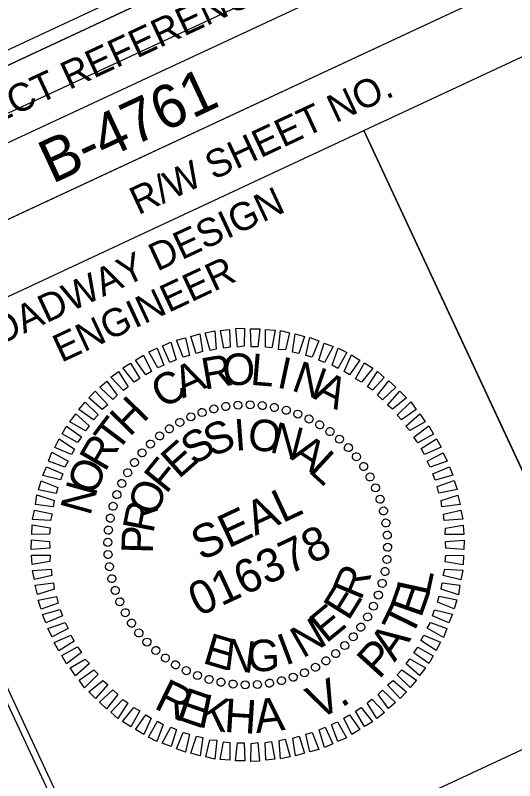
# Model space of a CAD drawing. Extents: x 2320593 to 2322597, y 921119 to 922832.
# Drawn here: x 2321990.9 to 2322080.4, y 922602.4 to 922739.5 of the extents above; entities that cross this region are included whole.
import ezdxf

# ---------------------------------------------------------------- set-up
doc = ezdxf.new("R2010")
doc.units = 0
for name, color, linetype in [('Prop Leader Line Medium', 7, 'Continuous'), ('Sheet Data Field CELL', 7, 'Continuous'), ('Sheet Layout Plan Border', 7, 'Continuous'), ('Sheet Plan And Profile CELL', 7, 'Continuous'), ('Sheet Plot Border Inside CELL', 7, 'Continuous'), ('Sheet Professional Seal CELL', 7, 'Continuous')]:
    doc.layers.add(name, color=color, linetype=linetype)

msp = doc.modelspace()

# ---------------------------------------------------------------- linework, layer by layer
at = {"layer": 'Prop Leader Line Medium'}
msp.add_lwpolyline([(2321590.4, 922532.13), (2321950.44, 922699.95), (2322002.96, 922587.28), (2321642.92, 922419.46)], close=True, dxfattribs=at)
at = {"layer": 'Sheet Layout Plan Border'}
msp.add_lwpolyline([(2322313.35, 922279.99), (2321040.83, 921692.7), (2320815.91, 922178.3), (2322085.86, 922766.57)], close=True, dxfattribs=at)
at = {"layer": 'Sheet Plan And Profile CELL'}
for p, q in [((2321952.14, 922699.22), (2322133.46, 922783.74)), ((2321957.42, 922687.9), (2322138.74, 922772.41)), ((2322053.38, 922718.83), (2322100.89, 922616.91))]:
    msp.add_line(p, q, dxfattribs=at)
for points in [[(2322128.15, 922795.12), (2320768.59, 922161.4), (2321212.2, 921209.71), (2322571.76, 921843.43)], [(2321946.83, 922710.6), (2322128.15, 922795.12), (2322138.74, 922772.41), (2321957.42, 922687.9)], [(2322053.38, 922718.83), (2322144.02, 922761.08), (2322191.55, 922659.12), (2322100.91, 922616.87)], [(2321962.7, 922676.57), (2322053.38, 922718.83), (2322100.91, 922616.87), (2322010.23, 922574.6)]]:
    msp.add_lwpolyline(points, close=True, dxfattribs=at)
at = {"layer": 'Sheet Plot Border Inside CELL'}
msp.add_lwpolyline([(2321074.13, 921142.59), (2322584.14, 921846.44), (2322138.43, 922802.66), (2320628.41, 922098.81)], close=True, dxfattribs=at)
at = {"layer": 'Sheet Professional Seal CELL'}
for p, q in [((2322028.63, 922669.42), (2322028.63, 922669.42)), ((2322030.82, 922669.67), (2322030.82, 922669.67)), ((2322033.02, 922669.7), (2322033.02, 922669.7)), ((2322035.21, 922669.62), (2322035.21, 922669.62)), ((2322024.44, 922668.35), (2322024.44, 922668.35)), ((2322026.53, 922668.94), (2322026.53, 922668.94)), ((2322037.37, 922669.24), (2322037.37, 922669.24)), ((2322039.52, 922668.76), (2322039.52, 922668.76)), ((2322041.56, 922668.06), (2322041.56, 922668.06)), ((2322020.41, 922666.58), (2322020.41, 922666.58)), ((2322022.38, 922667.55), (2322022.38, 922667.55)), ((2322043.62, 922667.19), (2322043.62, 922667.19)), ((2322018.58, 922665.4), (2322018.58, 922665.4)), ((2322045.49, 922666.14), (2322045.49, 922666.14)), ((2322016.76, 922664.11), (2322016.76, 922664.11)), ((2322047.34, 922664.9), (2322047.34, 922664.9)), ((2322015.11, 922662.68), (2322015.11, 922662.68)), ((2322049.07, 922663.55), (2322049.07, 922663.55)), ((2322013.63, 922661.11), (2322013.63, 922661.11)), ((2322050.64, 922662.08), (2322050.64, 922662.08)), ((2322052.07, 922660.43), (2322052.07, 922660.43)), ((2322012.29, 922659.38), (2322012.29, 922659.38)), ((2322053.36, 922658.61), (2322053.36, 922658.61)), ((2322011.05, 922657.53), (2322011.05, 922657.53)), ((2322009.99, 922655.66), (2322009.99, 922655.66)), ((2322054.54, 922656.78), (2322054.54, 922656.78)), ((2322055.51, 922654.81), (2322055.51, 922654.81)), ((2322009.13, 922653.6), (2322009.13, 922653.6)), ((2322008.43, 922651.56), (2322008.43, 922651.56)), ((2322056.31, 922652.75), (2322056.31, 922652.75)), ((2322056.9, 922650.66), (2322056.9, 922650.66)), ((2322007.94, 922649.41), (2322007.94, 922649.41)), ((2322057.38, 922648.56), (2322057.38, 922648.56)), ((2322007.57, 922647.25), (2322007.57, 922647.25)), ((2322057.63, 922646.36), (2322057.63, 922646.36)), ((2322007.49, 922645.06), (2322007.49, 922645.06)), ((2322032.57, 922644.61), (2322032.57, 922644.61)), ((2322057.66, 922644.17), (2322057.66, 922644.17)), ((2322007.52, 922642.86), (2322007.52, 922642.86)), ((2322057.58, 922641.98), (2322057.58, 922641.98)), ((2322007.77, 922640.67), (2322007.77, 922640.67)), ((2322057.21, 922639.82), (2322057.21, 922639.82)), ((2322008.25, 922638.57), (2322008.25, 922638.57)), ((2322008.84, 922636.48), (2322008.84, 922636.48)), ((2322056.72, 922637.66), (2322056.72, 922637.66)), ((2322056.02, 922635.63), (2322056.02, 922635.63)), ((2322009.63, 922634.42), (2322009.63, 922634.42)), ((2322010.61, 922632.44), (2322010.61, 922632.44)), ((2322055.15, 922633.57), (2322055.15, 922633.57)), ((2322054.1, 922631.7), (2322054.1, 922631.7)), ((2322011.79, 922630.62), (2322011.79, 922630.62)), ((2322052.86, 922629.85), (2322052.86, 922629.85)), ((2322013.08, 922628.8), (2322013.08, 922628.8)), ((2322051.52, 922628.12), (2322051.52, 922628.12)), ((2322014.51, 922627.15), (2322014.51, 922627.15)), ((2322016.08, 922625.67), (2322016.08, 922625.67)), ((2322050.04, 922626.55), (2322050.04, 922626.55)), ((2322017.81, 922624.33), (2322017.81, 922624.33)), ((2322048.39, 922625.12), (2322048.39, 922625.12)), ((2322019.66, 922623.09), (2322019.66, 922623.09)), ((2322044.74, 922622.65), (2322044.74, 922622.65)), ((2322046.57, 922623.83), (2322046.57, 922623.83)), ((2322021.53, 922622.03), (2322021.53, 922622.03)), ((2322042.77, 922621.67), (2322042.77, 922621.67)), ((2322023.59, 922621.17), (2322023.59, 922621.17)), ((2322025.63, 922620.47), (2322025.63, 922620.47)), ((2322027.78, 922619.98), (2322027.78, 922619.98)), ((2322038.62, 922620.29), (2322038.62, 922620.29)), ((2322040.71, 922620.88), (2322040.71, 922620.88)), ((2322029.94, 922619.61), (2322029.94, 922619.61)), ((2322032.13, 922619.53), (2322032.13, 922619.53)), ((2322034.32, 922619.56), (2322034.32, 922619.56)), ((2322036.52, 922619.81), (2322036.52, 922619.81))]:
    msp.add_line(p, q, dxfattribs=at)
for points in [[(2322025.88, 922679.45), (2322024.96, 922682.6), (2322026.67, 922682.96), (2322026.94, 922679.66)], [(2322028.33, 922679.87), (2322027.7, 922683), (2322029.32, 922683.2), (2322029.43, 922680)], [(2322030.75, 922680.01), (2322030.46, 922683.35), (2322031.98, 922683.4), (2322031.94, 922680.18)], [(2322033.19, 922680.1), (2322033.08, 922683.3), (2322034.78, 922683.32), (2322034.42, 922680.06)], [(2322035.76, 922680.03), (2322035.78, 922683.18), (2322037.5, 922683.04), (2322036.88, 922679.88)], [(2322038.1, 922679.63), (2322038.46, 922682.99), (2322040.08, 922682.59), (2322039.35, 922679.55)], [(2322020.99, 922678.22), (2322019.8, 922681.25), (2322021.42, 922681.67), (2322022.17, 922678.54)], [(2322023.34, 922678.87), (2322022.39, 922681.96), (2322023.99, 922682.43), (2322024.49, 922679.24)], [(2322040.59, 922679.13), (2322041.11, 922682.41), (2322042.75, 922681.96), (2322041.75, 922678.9)], [(2322042.97, 922678.53), (2322043.73, 922681.75), (2322045.32, 922681.17), (2322044.15, 922678.25)], [(2322018.66, 922677.3), (2322017.29, 922680.24), (2322018.81, 922680.89), (2322019.77, 922677.76)], [(2322045.34, 922677.71), (2322046.3, 922680.74), (2322047.89, 922680.16), (2322046.36, 922677.3)], [(2322016.47, 922676.33), (2322014.87, 922679.17), (2322016.38, 922679.82), (2322017.58, 922676.79)], [(2322047.69, 922676.81), (2322048.82, 922679.82), (2322050.34, 922679.04), (2322048.74, 922676.2)], [(2322014.31, 922675.05), (2322012.46, 922677.71), (2322013.91, 922678.61), (2322015.33, 922675.69)], [(2322049.87, 922675.68), (2322051.2, 922678.62), (2322052.68, 922677.7), (2322050.81, 922675.07)], [(2322012.26, 922673.76), (2322010.18, 922676.32), (2322011.61, 922677.16), (2322013.28, 922674.4)], [(2322051.91, 922674.37), (2322053.51, 922677.21), (2322055.01, 922676.25), (2322052.97, 922673.76)], [(2322010.32, 922672.25), (2322008.03, 922674.66), (2322009.43, 922675.69), (2322011.16, 922672.92)], [(2322054.02, 922672.93), (2322055.82, 922675.69), (2322057.06, 922674.56), (2322054.97, 922672.32)], [(2322008.42, 922670.64), (2322006.11, 922672.88), (2322007.32, 922673.94), (2322009.22, 922671.41)], [(2322055.84, 922671.4), (2322057.88, 922674.01), (2322059.14, 922672.83), (2322056.75, 922670.61)], [(2322006.53, 922668.88), (2322004.13, 922670.96), (2322005.24, 922672.14), (2322007.54, 922669.68)], [(2322057.64, 922669.65), (2322059.86, 922672.12), (2322061.01, 922670.94), (2322058.54, 922668.91)], [(2322004.98, 922667), (2322002.35, 922668.86), (2322003.46, 922670.15), (2322005.79, 922667.88)], [(2322059.38, 922667.81), (2322061.8, 922670.21), (2322062.77, 922668.84), (2322060.14, 922667.01)], [(2322003.54, 922665.01), (2322000.72, 922666.67), (2322001.79, 922668.05), (2322004.15, 922665.95)], [(2322060.94, 922665.89), (2322063.4, 922668.08), (2322064.39, 922666.67), (2322061.66, 922665.07)], [(2322002.07, 922662.94), (2321999.32, 922664.47), (2322000.1, 922665.88), (2322002.82, 922663.95)], [(2322062.36, 922663.91), (2322065.01, 922665.91), (2322065.87, 922664.44), (2322063.05, 922662.9)], [(2322000.99, 922660.78), (2321998.02, 922662.05), (2321998.8, 922663.57), (2322001.57, 922661.77)], [(2322063.65, 922661.86), (2322066.43, 922663.59), (2322067.23, 922662.09), (2322064.25, 922660.81)], [(2321999.83, 922658.53), (2321996.9, 922659.6), (2321997.49, 922661.19), (2322000.39, 922659.57)], [(2322064.75, 922659.61), (2322067.63, 922661.12), (2322068.35, 922659.58), (2322065.26, 922658.52)], [(2321999.07, 922656.25), (2321995.89, 922657.03), (2321996.54, 922658.6), (2321999.46, 922657.31)], [(2322065.76, 922657.33), (2322068.75, 922658.61), (2322069.36, 922657.07), (2322066.18, 922656.2)], [(2321998.29, 922653.79), (2321995.11, 922654.46), (2321995.56, 922656.1), (2321998.54, 922654.9)], [(2322066.55, 922655.04), (2322069.58, 922656.12), (2322070.11, 922654.5), (2322066.83, 922653.85)], [(2321997.73, 922651.43), (2321994.57, 922651.83), (2321994.81, 922653.55), (2321997.92, 922652.57)], [(2322067.26, 922652.56), (2322070.24, 922653.51), (2322070.64, 922651.82), (2322067.34, 922651.44)], [(2321997.22, 922648.99), (2321994.05, 922649.16), (2321994.36, 922650.85), (2321997.56, 922650.14)], [(2322067.69, 922650.11), (2322070.77, 922650.83), (2322071.15, 922649.19), (2322067.77, 922648.99)], [(2321997.04, 922646.53), (2321993.93, 922646.46), (2321993.95, 922648.18), (2321997.18, 922647.64)], [(2322068.02, 922647.62), (2322071.21, 922648.12), (2322071.28, 922646.44), (2322067.97, 922646.44)], [(2321997.1, 922644.02), (2321993.81, 922643.76), (2321993.83, 922645.48), (2321997.09, 922645.23)], [(2322068.05, 922645.21), (2322071.34, 922645.47), (2322071.32, 922643.75), (2322068.06, 922644)], [(2321997.13, 922641.61), (2321993.94, 922641.11), (2321993.87, 922642.79), (2321997.18, 922642.79)], [(2322068.11, 922642.7), (2322071.22, 922642.77), (2322071.2, 922641.05), (2322067.97, 922641.58)], [(2321997.46, 922639.11), (2321994.38, 922638.39), (2321994, 922640.04), (2321997.38, 922640.23)], [(2322067.93, 922640.24), (2322071.1, 922640.07), (2322070.79, 922638.37), (2322067.59, 922639.09)], [(2321997.89, 922636.66), (2321994.91, 922635.72), (2321994.51, 922637.41), (2321997.8, 922637.78)], [(2322067.42, 922637.8), (2322070.58, 922637.4), (2322070.33, 922635.68), (2322067.23, 922636.66)], [(2321998.6, 922634.18), (2321995.57, 922633.1), (2321995.04, 922634.73), (2321998.32, 922635.38)], [(2322066.86, 922635.44), (2322070.04, 922634.77), (2322069.59, 922633.13), (2322066.61, 922634.33)], [(2321999.39, 922631.9), (2321996.4, 922630.62), (2321995.79, 922632.16), (2321998.97, 922633.03)], [(2322066.08, 922632.98), (2322069.25, 922632.2), (2322068.61, 922630.63), (2322065.69, 922631.92)], [(2322000.4, 922629.62), (2321997.52, 922628.11), (2321996.8, 922629.65), (2321999.89, 922630.7)], [(2322065.32, 922630.7), (2322068.24, 922629.63), (2322067.66, 922628.04), (2322064.76, 922629.66)], [(2322001.5, 922627.37), (2321998.72, 922625.64), (2321997.91, 922627.13), (2322000.9, 922628.42)], [(2322064.16, 922628.45), (2322067.13, 922627.18), (2322066.35, 922625.66), (2322063.58, 922627.46)], [(2322002.79, 922625.32), (2322000.14, 922623.32), (2321999.28, 922624.79), (2322002.1, 922626.33)], [(2322063.07, 922626.28), (2322065.83, 922624.75), (2322065.05, 922623.34), (2322062.33, 922625.27)], [(2322004.21, 922623.34), (2322001.75, 922621.15), (2322000.76, 922622.56), (2322003.49, 922624.16)], [(2322061.61, 922624.22), (2322064.43, 922622.56), (2322063.36, 922621.18), (2322061, 922623.28)], [(2322005.77, 922621.42), (2322003.35, 922619.02), (2322002.38, 922620.39), (2322005, 922622.22)], [(2322060.17, 922622.22), (2322062.8, 922620.36), (2322061.69, 922619.07), (2322059.36, 922621.35)], [(2322007.5, 922619.58), (2322005.29, 922617.11), (2322004.14, 922618.28), (2322006.61, 922620.32)], [(2322058.62, 922620.34), (2322061.02, 922618.26), (2322059.91, 922617.09), (2322057.61, 922619.54)], [(2322009.31, 922617.83), (2322007.27, 922615.22), (2322006.01, 922616.4), (2322008.39, 922618.61)], [(2322056.73, 922618.58), (2322059.04, 922616.35), (2322057.83, 922615.29), (2322055.93, 922617.82)], [(2322011.13, 922616.3), (2322009.33, 922613.53), (2322008.08, 922614.66), (2322010.18, 922616.91)], [(2322054.83, 922616.98), (2322057.12, 922614.57), (2322055.72, 922613.53), (2322053.99, 922616.31)], [(2322013.24, 922614.86), (2322011.64, 922612.02), (2322010.14, 922612.97), (2322012.18, 922615.47)], [(2322052.89, 922615.47), (2322054.97, 922612.91), (2322053.53, 922612.07), (2322051.87, 922614.83)], [(2322015.28, 922613.55), (2322013.95, 922610.61), (2322012.47, 922611.52), (2322014.33, 922614.16)], [(2322050.84, 922614.18), (2322052.69, 922611.51), (2322051.24, 922610.61), (2322049.82, 922613.54)], [(2322017.46, 922612.42), (2322016.33, 922609.4), (2322014.81, 922610.18), (2322016.41, 922613.03)], [(2322019.81, 922611.52), (2322018.85, 922608.48), (2322017.26, 922609.07), (2322018.79, 922611.93)], [(2322046.48, 922611.93), (2322047.86, 922608.99), (2322046.34, 922608.33), (2322045.38, 922611.47)], [(2322048.68, 922612.9), (2322050.28, 922610.06), (2322048.76, 922609.41), (2322047.57, 922612.44)], [(2322022.18, 922610.7), (2322021.42, 922607.47), (2322019.83, 922608.06), (2322021, 922610.98)], [(2322024.56, 922610.1), (2322024.04, 922606.82), (2322022.4, 922607.27), (2322023.4, 922610.33)], [(2322041.81, 922610.36), (2322042.76, 922607.27), (2322041.15, 922606.8), (2322040.66, 922609.99)], [(2322044.16, 922611.01), (2322045.35, 922607.98), (2322043.73, 922607.56), (2322042.98, 922610.68)], [(2322027.05, 922609.6), (2322026.69, 922606.23), (2322025.07, 922606.64), (2322025.8, 922609.68)], [(2322029.39, 922609.2), (2322029.37, 922606.05), (2322027.65, 922606.18), (2322028.27, 922609.34)], [(2322031.96, 922609.13), (2322032.07, 922605.93), (2322030.37, 922605.91), (2322030.73, 922609.16)], [(2322034.4, 922609.22), (2322034.69, 922605.88), (2322033.16, 922605.83), (2322033.21, 922609.05)], [(2322036.82, 922609.36), (2322037.45, 922606.23), (2322035.83, 922606.03), (2322035.72, 922609.23)], [(2322039.27, 922609.78), (2322040.19, 922606.62), (2322038.48, 922606.27), (2322038.21, 922609.56)]]:
    msp.add_lwpolyline(points, close=True, dxfattribs=at)
for centre, major_axis in [((2322026.51, 922668.95), (-0.174, 0.699)), ((2322028.65, 922669.39), (-0.113, 0.711)), ((2322030.83, 922669.63), (-0.05, 0.718)), ((2322033.02, 922669.69), (0.013, 0.72)), ((2322035.2, 922669.56), (0.075, 0.716)), ((2322037.36, 922669.23), (0.137, 0.707)), ((2322039.49, 922668.72), (0.199, 0.692)), ((2322022.38, 922667.53), (-0.293, 0.658)), ((2322024.41, 922668.33), (-0.234, 0.681)), ((2322041.57, 922668.03), (0.258, 0.672)), ((2322043.57, 922667.15), (0.316, 0.647)), ((2322020.42, 922666.55), (-0.349, 0.63)), ((2322045.49, 922666.11), (0.371, 0.617)), ((2322018.55, 922665.41), (-0.403, 0.597)), ((2322047.32, 922664.9), (0.423, 0.582)), ((2322016.79, 922664.11), (-0.453, 0.56)), ((2322049.03, 922663.54), (0.472, 0.543)), ((2322015.16, 922662.66), (-0.5, 0.518)), ((2322050.62, 922662.03), (0.518, 0.5)), ((2322013.65, 922661.07), (-0.543, 0.472)), ((2322052.07, 922660.39), (0.56, 0.453)), ((2322012.29, 922659.36), (-0.582, 0.423)), ((2322011.08, 922657.53), (-0.617, 0.371)), ((2322053.37, 922658.64), (0.597, 0.403)), ((2322054.51, 922656.77), (0.63, 0.349)), ((2322010.03, 922655.61), (-0.647, 0.316)), ((2322055.49, 922654.81), (0.658, 0.293)), ((2322009.16, 922653.61), (-0.672, 0.258)), ((2322056.29, 922652.78), (0.681, 0.234)), ((2322008.47, 922651.53), (-0.692, 0.199)), ((2322056.91, 922650.68), (0.699, 0.174)), ((2322007.96, 922649.4), (-0.707, 0.137)), ((2322057.35, 922648.53), (0.711, 0.113)), ((2322007.63, 922647.24), (-0.716, 0.075)), ((2322057.59, 922646.36), (0.718, 0.05)), ((2322007.5, 922645.06), (-0.72, 0.013)), ((2322057.65, 922644.17), (0.72, -0.013)), ((2322007.56, 922642.87), (-0.718, -0.05)), ((2322057.52, 922641.99), (0.716, -0.075)), ((2322007.8, 922640.69), (-0.711, -0.113)), ((2322057.19, 922639.82), (0.707, -0.137)), ((2322008.24, 922638.55), (-0.699, -0.174)), ((2322056.68, 922637.7), (0.692, -0.199)), ((2322008.86, 922636.45), (-0.681, -0.234)), ((2322055.99, 922635.62), (0.672, -0.258)), ((2322009.66, 922634.42), (-0.658, -0.293)), ((2322055.11, 922633.62), (0.647, -0.316)), ((2322010.64, 922632.46), (-0.63, -0.349)), ((2322054.07, 922631.69), (0.617, -0.371)), ((2322011.78, 922630.59), (-0.597, -0.403)), ((2322013.08, 922628.83), (-0.56, -0.453)), ((2322052.86, 922629.87), (0.582, -0.423)), ((2322051.5, 922628.16), (0.543, -0.472)), ((2322014.53, 922627.19), (-0.518, -0.5)), ((2322049.99, 922626.57), (0.5, -0.518)), ((2322016.12, 922625.69), (-0.472, -0.543)), ((2322048.35, 922625.12), (0.453, -0.56)), ((2322017.83, 922624.33), (-0.423, -0.582)), ((2322046.6, 922623.82), (0.403, -0.597)), ((2322019.65, 922623.12), (-0.371, -0.617)), ((2322021.58, 922622.07), (-0.316, -0.647)), ((2322044.73, 922622.68), (0.349, -0.63)), ((2322023.58, 922621.2), (-0.258, -0.672)), ((2322025.66, 922620.51), (-0.199, -0.692)), ((2322040.74, 922620.9), (0.234, -0.681)), ((2322042.77, 922621.7), (0.293, -0.658)), ((2322027.79, 922620), (-0.137, -0.707)), ((2322029.95, 922619.67), (-0.075, -0.716)), ((2322032.13, 922619.54), (-0.013, -0.72)), ((2322034.32, 922619.59), (0.05, -0.718)), ((2322036.49, 922619.84), (0.113, -0.711)), ((2322038.64, 922620.28), (0.174, -0.699))]:
    msp.add_ellipse(centre, major_axis=major_axis, ratio=0.999708, dxfattribs=at)

# ---------------------------------------------------------------- texts
at = {"layer": 'Sheet Data Field CELL'}
msp.add_text('B-4761', height=7.75, rotation=24.9913, dxfattribs=at).set_placement((2321997.57, 922709.21))
at = {"layer": 'Sheet Plan And Profile CELL'}
for s, height, p in [('PROJECT REFERENCE NO.', 5.0001, (2321970.63, 922712.09)), ('R/W SHEET NO.', 5.0001, (2322012.97, 922703.64)), ('ROADWAY DESIGN', 5.0001, (2321983.37, 922678.15)), ('ENGINEER', 5, (2321999.2, 922677.2))]:
    msp.add_text(s, height=height, rotation=24.9913, dxfattribs=at).set_placement(p)
at = {"layer": 'Sheet Professional Seal CELL'}
for s, height, rotation, p in [('O', 5.64, 2.4125, (2322028.17, 922673.12)), ('L', 5.64, 355.2122, (2322032.94, 922673.3)), ('R', 5.64, 9.6124, (2322024.81, 922672.39)), ('I', 5.64, 348.0114, (2322037.62, 922672.84)), ('A', 5.64, 24.0116, (2322020.92, 922670.79)), ('N', 5.64, 340.8102, (2322040.23, 922672.34)), ('C', 5.64, 31.2112, (2322017.47, 922668.85)), ('A', 5.64, 333.6085, (2322044.15, 922670.92)), ('H', 5.64, 45.6108, (2322011.43, 922663.83)), ('T', 5.64, 52.8111, (2322009.18, 922660.96)), ('S', 5.64, 22.8917, (2322026.16, 922660.27)), ('I', 5.64, 4.1809, (2322030.35, 922661.45)), ('O', 5.64, 354.8248, (2322032.46, 922661.66)), ('N', 5.64, 345.4679, (2322036.34, 922661.26)), ('S', 5.64, 32.2469, (2322022.92, 922658.7)), ('R', 5.64, 60.0118, (2322007.03, 922657.53)), ('E', 5.64, 41.6024, (2322020.23, 922656.29)), ('A', 5.64, 326.7516, (2322040.02, 922660.11)), ('L', 5.64, 317.3921, (2322043.25, 922657.81)), ('O', 5.64, 67.213, (2322005.21, 922653.26)), ('F', 5.64, 50.9583, (2322017.97, 922653.58)), ('N', 5.64, 74.4148, (2322004.35, 922649.66)), ('O', 5.64, 69.6725, (2322016.22, 922649.51)), ('SEAL', 5.998, 24.9913, (2322024.24, 922641.67)), ('R', 5.64, 79.0309, (2322015.67, 922646.55)), ('P', 5.64, 88.3902, (2322015.57, 922642.98)), ('016378', 5.998, 24.9913, (2322023.78, 922631.68)), ('R', 5.64, 67.4727, (2322052.85, 922634.48)), ('L', 6, 77.7163, (2322065.04, 922635.29)), ('E', 6, 70.607, (2322063.63, 922631.35)), ('E', 5.64, 58.1154, (2322050.63, 922630.85)), ('E', 5.64, 39.4031, (2322046.65, 922626.85)), ('T', 6, 63.8067, (2322061.84, 922627.76)), ('N', 5.64, 30.0477, (2322042.42, 922624.21)), ('E', 5.64, 343.2682, (2322024.32, 922623.5)), ('I', 5.64, 20.6925, (2322039.32, 922622.93)), ('A', 6, 54.9664, (2322058.91, 922623.47)), ('N', 5.64, 352.6253, (2322028.18, 922622.32)), ('G', 5.64, 1.9815, (2322032.58, 922621.89)), ('P', 6, 47.8571, (2322056.09, 922620.37)), ('R', 6, 333.4718, (2322015.55, 922615.44)), ('V', 6, 25.3699, (2322045.03, 922613.22)), ('E', 6, 340.952, (2322019.5, 922613.48)), ('K', 6, 348.0614, (2322023.45, 922612.1)), ('A', 6, 6.3293, (2322034.1, 922610.88)), ('H', 6, 356.3453, (2322028.23, 922611.12)), ('.', 6, 33.623, (2322049.4, 922615.33))]:
    msp.add_text(s, height=height, rotation=rotation, dxfattribs=at).set_placement(p)

doc.saveas('drawing.dxf')
